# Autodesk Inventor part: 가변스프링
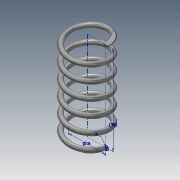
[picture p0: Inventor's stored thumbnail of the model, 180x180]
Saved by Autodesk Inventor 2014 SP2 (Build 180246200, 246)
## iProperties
Created: 2018-06
Part Number: 가변스프링
Material: 강철, 탄소
Document SubType Name: Modeling
Designer: 거성
Mass: 7.37548 g
Surface Area: 18.9884 cm^2
Volume: 0.937164 cm^3
Density: 7.87 g/cm^3
Appearance: 반연마
Author: 거성
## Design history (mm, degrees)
sketch "스케치1"
  geometry: L1 (0, 0)-(8, 0); L2 (8, 0)-(8, 38); L3 (8, 38)-(0, 38); L4 (0, 38)-(0, 0); C1 r 1 at (8, 0)
  constraints: 8 end point, 2 parallel, 1 centre point, 1 coincident, 1 horizontal, 1 perpendicular
  dimensions: "d0" = 2 diameter of C1; "d1" = 38 distance between parallel lines of L1 L3 (derived); "d2" = 16 diameter of L2 L4
feature "코일1" pitch "d3" = 10; turns "d5" = 6; dims "d4" = 38 (= d1), "d6" = 0, angle "d7" = 90 deg, angle "d8" = 90 deg, "d9" = 0, "d10" = 0
sketch "스케치2"
  geometry: L1 (-7, 0)-(-9, 0) reference; 1 further point
  constraints: 1 horizontal alignment
extrude "돌출1" cut sketch "스케치2" stored distance "d11" = 10; taper "d12" = 0 deg
node "작업 평면1"
sketch "스케치3"
  geometry: L1 (-1, 0)-(1, 0) reference; 1 further point
  constraints: 1 horizontal alignment
extrude "돌출2" cut sketch "스케치3" stored distance "d14" = 10; taper "d15" = 0 deg
node "솔리드1"
node "절단 모서리 투영1"
node "절단 모서리 투영2"
other parameters: "d13" = 0
